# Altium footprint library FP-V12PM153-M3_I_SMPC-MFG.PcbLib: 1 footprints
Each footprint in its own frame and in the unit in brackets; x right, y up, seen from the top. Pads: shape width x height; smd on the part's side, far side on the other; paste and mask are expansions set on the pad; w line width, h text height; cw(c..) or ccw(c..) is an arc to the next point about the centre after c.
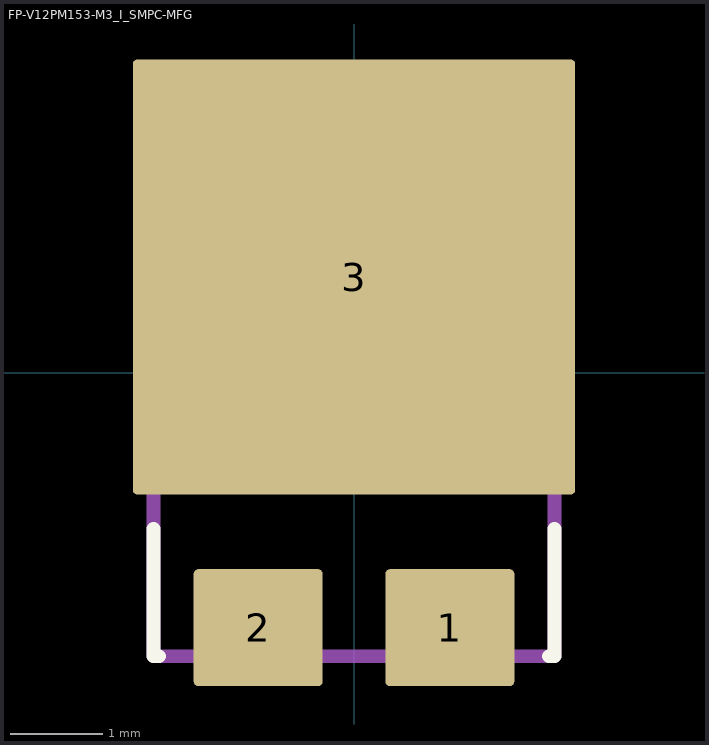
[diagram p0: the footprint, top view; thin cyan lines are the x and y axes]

## FP-V12PM153-M3_I_SMPC-MFG [mm]
pads (3):
  rrect8% 1.4x1.27 smd paste+0 mask+0: 1(1.04,-2.765) 2(-1.04,-2.765)
  rrect2% 4.8x4.72 smd paste+0 mask+0: 3(0,1.04)
Top Overlay:
  lines w0.15: -2.175,-1.695 -2.175,-3.075 -2.115,-3.075 ; 2.115,-3.075 2.175,-3.075 2.175,-1.695
Mechanical 5:
  lines w0.15: -2.175,-3.075 -2.175,3.075 2.175,3.075 2.175,-3.075 -2.175,-3.075
  text ".Designator" at 0.05,0.217 h0.5
3D body "Diode_V12PM153-M3_I_SMPC.STEP": height 0.25, standoff 0, extent -2.5,-3.5 2.5,3.5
